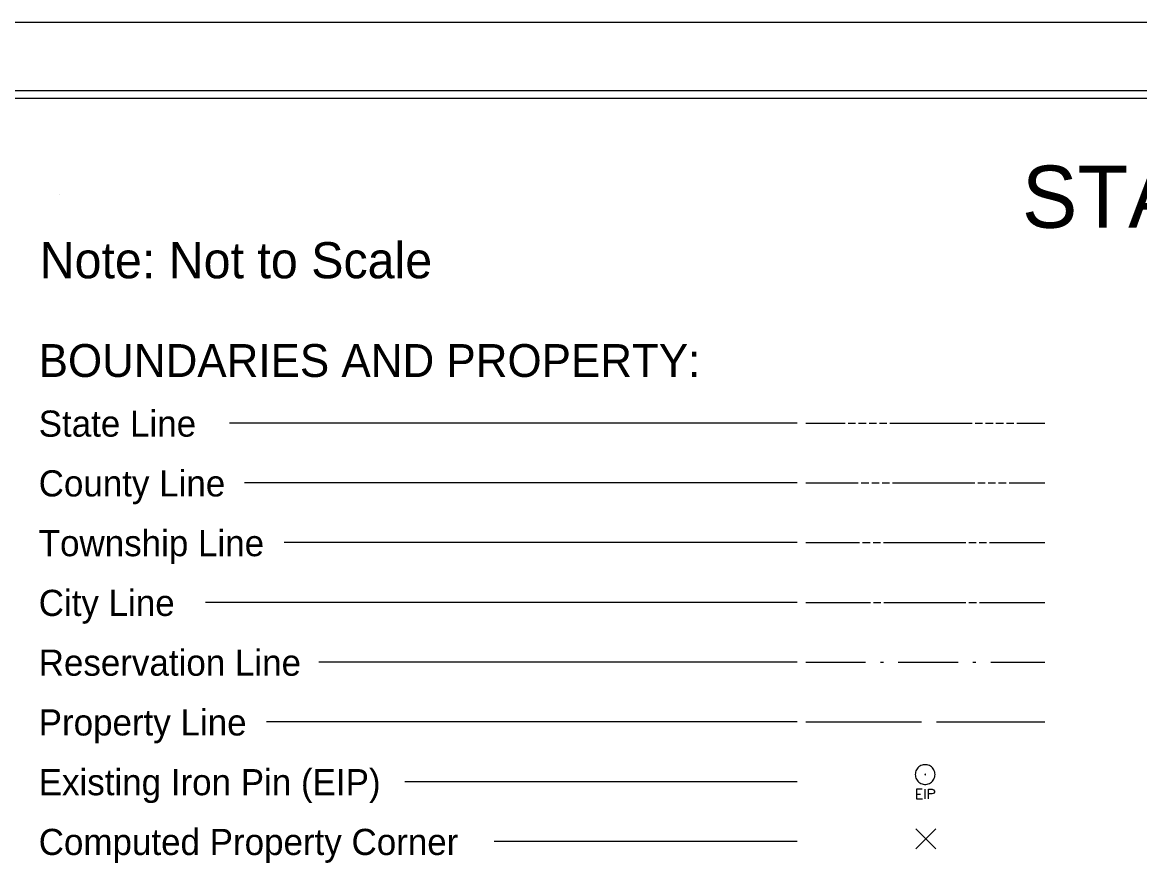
# Model space of a CAD drawing. Extents: x 2594871.4 to 2594905.1, y 784137.6 to 784159.6.
# Drawn here: x 2594875.29 to 2594882.63, y 784153.98 to 784159.56 of the extents above; entities that cross this region are included whole.
import ezdxf

# ---------------------------------------------------------------- set-up
doc = ezdxf.new("R2010")
doc.units = 0
for name, color, linetype in [('Default', 7, 'Continuous'), ('Sheet Plot Border Inside CELL', 7, 'Continuous'), ('Sheet Plot Border Outside CELL', 7, 'Continuous'), ('Sheet Symbology CELL', 7, 'Continuous')]:
    doc.layers.add(name, color=color, linetype=linetype)

msp = doc.modelspace()

# ---------------------------------------------------------------- linework, layer by layer
at = {"layer": 'Default'}
for p, q in [((2594875.5314, 784158.4317), (2594875.5314, 784158.4317)), ((2594880.3766, 784156.9308), (2594876.65, 784156.9308)), ((2594880.433, 784156.9308), (2594880.692, 784156.9308)), ((2594880.7116, 784156.9308), (2594880.7606, 784156.9308)), ((2594880.7802, 784156.9308), (2594880.8293, 784156.9308)), ((2594880.8489, 784156.9308), (2594880.8979, 784156.9308)), ((2594880.9175, 784156.9308), (2594880.9666, 784156.9308)), ((2594880.9862, 784156.9308), (2594881.5256, 784156.9308)), ((2594881.5452, 784156.9308), (2594881.5943, 784156.9308)), ((2594881.6139, 784156.9308), (2594881.6629, 784156.9308)), ((2594881.6825, 784156.9308), (2594881.7316, 784156.9308)), ((2594881.7512, 784156.9308), (2594881.8002, 784156.9308)), ((2594881.8199, 784156.9308), (2594882.0023, 784156.9308)), ((2594880.3766, 784156.5385), (2594876.7478, 784156.5385)), ((2594880.433, 784156.5385), (2594880.778, 784156.5385)), ((2594880.7976, 784156.5385), (2594880.8467, 784156.5385)), ((2594880.8663, 784156.5385), (2594880.9153, 784156.5385)), ((2594880.935, 784156.5385), (2594880.984, 784156.5385)), ((2594881.0036, 784156.5385), (2594881.543, 784156.5385)), ((2594881.5626, 784156.5385), (2594881.6117, 784156.5385)), ((2594881.6313, 784156.5385), (2594881.6803, 784156.5385)), ((2594881.7, 784156.5385), (2594881.749, 784156.5385)), ((2594881.7686, 784156.5385), (2594882.0023, 784156.5385)), ((2594880.3766, 784156.1462), (2594877.0087, 784156.1462)), ((2594880.433, 784156.1462), (2594880.7871, 784156.1462)), ((2594880.8067, 784156.1462), (2594880.8558, 784156.1462)), ((2594880.8754, 784156.1462), (2594880.9244, 784156.1462)), ((2594880.944, 784156.1462), (2594881.4834, 784156.1462)), ((2594881.5031, 784156.1462), (2594881.5521, 784156.1462)), ((2594881.5717, 784156.1462), (2594881.6208, 784156.1462)), ((2594881.6404, 784156.1462), (2594882.0023, 784156.1462)), ((2594880.3766, 784155.7538), (2594876.4914, 784155.7538)), ((2594880.433, 784155.7538), (2594880.8575, 784155.7538)), ((2594880.8771, 784155.7538), (2594880.9261, 784155.7538)), ((2594880.9457, 784155.7538), (2594881.4852, 784155.7538)), ((2594881.5048, 784155.7538), (2594881.5538, 784155.7538)), ((2594881.5734, 784155.7538), (2594882.0023, 784155.7538)), ((2594880.3766, 784155.3615), (2594877.2367, 784155.3615)), ((2594880.433, 784155.3615), (2594880.8254, 784155.3615)), ((2594880.9234, 784155.3615), (2594880.943, 784155.3615)), ((2594881.0411, 784155.3615), (2594881.4334, 784155.3615)), ((2594881.5315, 784155.3615), (2594881.5511, 784155.3615)), ((2594881.6492, 784155.3615), (2594882.0023, 784155.3615)), ((2594880.3766, 784154.9692), (2594876.8917, 784154.9692)), ((2594880.433, 784154.9692), (2594881.1931, 784154.9692)), ((2594881.2912, 784154.9692), (2594882.0023, 784154.9692)), ((2594880.3766, 784154.5769), (2594877.8014, 784154.5769)), ((2594881.1615, 784154.4958), (2594881.1872, 784154.4958)), ((2594881.2179, 784154.4641), (2594881.2179, 784154.5269)), ((2594881.2866, 784154.1371), (2594881.1569, 784154.2668)), ((2594881.1569, 784154.1371), (2594881.2866, 784154.2668)), ((2594880.3766, 784154.1846), (2594878.3868, 784154.1846))]:
    msp.add_line(p, q, dxfattribs=at)
for points in [[(2594881.2823, 784154.624), (2594881.2818, 784154.6323), (2594881.2802, 784154.6401), (2594881.2776, 784154.648), (2594881.2745, 784154.6553), (2594881.2698, 784154.662), (2594881.2646, 784154.6683), (2594881.2588, 784154.6741), (2594881.2521, 784154.6787), (2594881.2453, 784154.6829), (2594881.2375, 784154.6855), (2594881.2297, 784154.6876), (2594881.2218, 784154.6886), (2594881.2135, 784154.6886), (2594881.2052, 784154.6876), (2594881.1973, 784154.6855), (2594881.19, 784154.6829), (2594881.1827, 784154.6787), (2594881.176, 784154.6741), (2594881.1702, 784154.6683), (2594881.165, 784154.662), (2594881.1608, 784154.6553), (2594881.1572, 784154.648), (2594881.1546, 784154.6401), (2594881.153, 784154.6323), (2594881.1525, 784154.624), (2594881.153, 784154.6157), (2594881.1546, 784154.6078), (2594881.1572, 784154.6), (2594881.1608, 784154.5927), (2594881.165, 784154.5859), (2594881.1702, 784154.5797), (2594881.176, 784154.5739), (2594881.1827, 784154.5693), (2594881.19, 784154.5651), (2594881.1973, 784154.5625), (2594881.2052, 784154.5604), (2594881.2135, 784154.5594), (2594881.2218, 784154.5594), (2594881.2297, 784154.5604), (2594881.2375, 784154.5625), (2594881.2453, 784154.5651), (2594881.2521, 784154.5693), (2594881.2588, 784154.5739), (2594881.2646, 784154.5797), (2594881.2698, 784154.5859), (2594881.2745, 784154.5927), (2594881.2776, 784154.6), (2594881.2802, 784154.6078), (2594881.2818, 784154.6157), (2594881.2823, 784154.624)], [(2594881.2187, 784154.6256), (2594881.2171, 784154.6261), (2594881.2161, 784154.625), (2594881.2156, 784154.6235), (2594881.2166, 784154.6224), (2594881.2182, 784154.6219), (2594881.2192, 784154.6229), (2594881.2197, 784154.6245), (2594881.2187, 784154.6256)], [(2594881.1976, 784154.5269), (2594881.1615, 784154.5269), (2594881.1615, 784154.4641), (2594881.2001, 784154.4641)], [(2594881.2386, 784154.4641), (2594881.2386, 784154.5269), (2594881.2638, 784154.5269), (2594881.2712, 784154.5244), (2594881.2777, 784154.5145), (2594881.2777, 784154.5086), (2594881.2717, 784154.4987), (2594881.2638, 784154.4963), (2594881.2386, 784154.4963)]]:
    msp.add_lwpolyline(points, dxfattribs=at)
at = {"layer": 'Sheet Plot Border Inside CELL'}
msp.add_lwpolyline([(2594871.6321, 784138.0107), (2594904.9621, 784138.0107), (2594904.9621, 784159.1127), (2594871.6321, 784159.1127)], close=True, dxfattribs=at)
at = {"layer": 'Sheet Plot Border Outside CELL'}
msp.add_lwpolyline([(2594905.0521, 784159.5617), (2594871.3721, 784159.5617), (2594871.3721, 784137.5617), (2594905.0521, 784137.5617)], close=True, dxfattribs=at)
at = {"layer": 'Sheet Symbology CELL'}
msp.add_lwpolyline([(2594904.7121, 784159.0617), (2594874.7121, 784159.0617), (2594874.7121, 784138.0821), (2594904.7121, 784138.0821)], close=True, dxfattribs=at)

# ---------------------------------------------------------------- texts
at = {"layer": 'Default'}
for s, height, p in [('STATE OF NORTH CAROLINA, DIVISION OF HIGHWAYS', 0.408275, (2594881.8527, 784158.2129)), ('Note: Not to Scale', 0.237495, (2594875.4032, 784157.8814)), ('BOUNDARIES AND PROPERTY:', 0.21577, (2594875.3965, 784157.2338)), ('State Line', 0.17164, (2594875.3968, 784156.8418)), ('County Line', 0.171636, (2594875.3968, 784156.4495)), ('Township Line', 0.171636, (2594875.3968, 784156.0571)), ('City Line', 0.17164, (2594875.3968, 784155.6648)), ('Reservation Line', 0.171636, (2594875.3968, 784155.2725)), ('Property Line', 0.171636, (2594875.3968, 784154.8802)), ('Existing Iron Pin (EIP)', 0.171636, (2594875.3968, 784154.4879)), ('Computed Property Corner', 0.171636, (2594875.3968, 784154.0956))]:
    msp.add_text(s, height=height, rotation=360, dxfattribs=at).set_placement(p)

doc.saveas('drawing.dxf')
